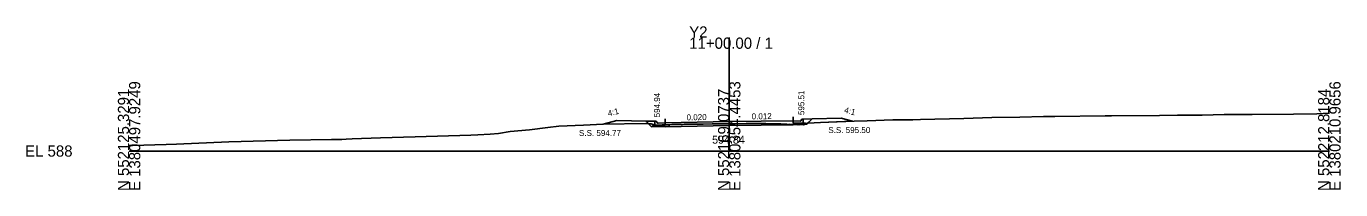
# Model space of a CAD drawing. Extents: x -26 to 303, y -10 to 2047.
# Drawn here: x -25.7 to 302.8, y 490.3 to 531.2 of the extents above; entities that cross this region are included whole.
import ezdxf

# ---------------------------------------------------------------- set-up
doc = ezdxf.new("R2010")
doc.units = 0
for name, color, linetype in [('Exist Cross Section Cell', 7, 'Continuous'), ('Exist XS Center Line Elevation Label', 7, 'Continuous'), ('Exist XS Ground Line', 7, 'Continuous'), ('Prop XS Dump Level', 7, 'Continuous'), ('Prop XS Earthwork Shape', 7, 'Continuous'), ('Prop XS EOT Tick Mark', 7, 'Continuous'), ('Prop XS Finish Grade', 7, 'Continuous'), ('Prop XS Finish Grade CurbGutter', 7, 'Continuous'), ('Prop XS Finish Grade Earthwork', 7, 'Continuous'), ('Prop XS Finish Grade Pavement', 7, 'Continuous'), ('Prop XS Hydro Elevations', 7, 'Continuous'), ('Prop XS Pvmt Edge Slope', 7, 'Continuous'), ('Prop XS SE Text', 7, 'Continuous'), ('Prop XS Side Slope Text', 7, 'Continuous'), ('Prop XS SS Elevation Text', 7, 'Continuous'), ('Prop XS Subgrade CurbGutter', 7, 'Continuous'), ('Prop XS Subgrade Earthwork', 7, 'Continuous')]:
    doc.layers.add(name, color=color, linetype=linetype)

msp = doc.modelspace()

# ---------------------------------------------------------------- linework, layer by layer
at = {"layer": 'Exist Cross Section Cell'}
for p, q in [((150, 500), (150, 528.41)), ((0, 500), (150, 500)), ((150, 500), (300, 500))]:
    msp.add_line(p, q, dxfattribs=at)
at = {"layer": 'Exist XS Ground Line'}
for p, q in [((280.7, 509.18), (291.03, 509.27)), ((291.03, 509.27), (296.84, 509.35)), ((296.84, 509.35), (300, 509.47)), ((104.7, 505.92), (107.39, 506.22)), ((107.39, 506.22), (113.6, 506.51)), ((113.6, 506.51), (118.53, 506.77)), ((118.53, 506.77), (129.05, 506.86)), ((129.05, 506.86), (130.51, 506.84)), ((130.51, 506.84), (131.6, 506.44)), ((131.6, 506.44), (133.25, 506.53)), ((133.25, 506.53), (135.12, 506.6)), ((135.12, 506.6), (135.66, 506.62)), ((135.66, 506.62), (136.01, 506.63)), ((136.01, 506.63), (137.19, 506.66)), ((137.19, 506.66), (138.29, 506.68)), ((138.29, 506.68), (138.77, 506.69)), ((138.77, 506.69), (140.9, 506.73)), ((140.9, 506.73), (142.03, 506.74)), ((142.03, 506.74), (143.51, 506.76)), ((143.51, 506.76), (145.74, 506.78)), ((145.74, 506.78), (146.31, 506.79)), ((146.31, 506.79), (148.73, 506.83)), ((148.73, 506.83), (150.04, 506.84)), ((150.04, 506.84), (151.33, 506.85)), ((151.33, 506.85), (154.27, 506.86)), ((154.27, 506.86), (156.55, 506.88)), ((156.55, 506.88), (157.55, 506.88)), ((157.55, 506.88), (159.17, 506.87)), ((159.17, 506.87), (160.03, 506.85)), ((160.03, 506.85), (161.77, 506.82)), ((161.77, 506.82), (162.89, 506.79)), ((162.89, 506.79), (164.05, 506.75)), ((164.05, 506.75), (164.41, 506.74)), ((164.41, 506.74), (166.2, 506.68)), ((166.2, 506.68), (166.81, 506.66)), ((166.81, 506.66), (168.52, 506.57)), ((168.52, 506.57), (169.6, 506.97)), ((169.6, 506.97), (172.79, 507.14)), ((172.79, 507.14), (181.26, 507.52)), ((181.26, 507.52), (184.44, 507.59)), ((184.44, 507.59), (190.9, 507.78)), ((190.9, 507.78), (194.87, 507.83)), ((194.87, 507.83), (195.92, 507.84)), ((195.92, 507.84), (197.84, 507.87)), ((197.84, 507.87), (208.6, 508.11)), ((208.6, 508.11), (215.65, 508.37)), ((215.65, 508.37), (222.67, 508.45)), ((222.67, 508.45), (228.56, 508.64)), ((228.56, 508.64), (231.39, 508.69)), ((231.39, 508.69), (243.98, 508.79)), ((243.98, 508.79), (245.55, 508.81)), ((245.55, 508.81), (257.55, 508.92)), ((257.55, 508.92), (262.08, 509.01)), ((262.08, 509.01), (268.22, 509.02)), ((268.22, 509.02), (273.71, 509.13)), ((273.71, 509.13), (279.21, 509.19)), ((279.21, 509.19), (280.7, 509.18)), ((24.93, 502.27), (40.2, 502.72)), ((40.2, 502.72), (50.57, 502.93)), ((50.57, 502.93), (53.21, 502.93)), ((53.21, 502.93), (54.3, 502.96)), ((54.3, 502.96), (55.8, 503.04)), ((55.8, 503.04), (62.82, 503.27)), ((62.82, 503.27), (71.48, 503.57)), ((71.48, 503.57), (85.38, 503.97)), ((85.38, 503.97), (87.17, 504.02)), ((87.17, 504.02), (90.21, 504.26)), ((90.21, 504.26), (92.35, 504.42)), ((92.35, 504.42), (95.26, 504.87)), ((95.26, 504.87), (100.11, 505.35)), ((100.11, 505.35), (104.7, 505.92)), ((0, 501.35), (0.85, 501.38)), ((0.85, 501.38), (9.3, 501.65)), ((9.3, 501.65), (11.83, 501.72)), ((11.83, 501.72), (24.93, 502.27))]:
    msp.add_line(p, q, dxfattribs=at)
at = {"layer": 'Prop XS Dump Level'}
for p, q in [((133.95, 507.06), (150, 507.38)), ((133.95, 506.06), (150, 506.38)), ((150, 507.38), (166.01, 507.57)), ((150, 506.38), (166.01, 506.57))]:
    msp.add_line(p, q, dxfattribs=at)
at = {"layer": 'Prop XS Earthwork Shape'}
for points in [[(121.95, 507.64), (118.46, 506.77), (118.53, 506.77), (129.05, 506.86), (129.84, 506.85), (129.21, 507.48)], [(134.95, 506.16), (130.61, 506.08), (129.84, 506.85), (130.51, 506.84), (131.6, 506.44), (133.25, 506.53), (134.95, 506.59)], [(165.01, 506.64), (165.01, 506.72), (166.2, 506.68), (166.81, 506.66), (166.84, 506.66)], [(168.52, 506.57), (168.84, 506.68), (166.84, 506.66)], [(169.6, 506.97), (169.62, 506.97), (169.34, 506.69), (168.84, 506.68)], [(170.71, 508.05), (178.01, 508.21), (180.83, 507.5), (172.79, 507.14), (169.62, 506.97)]]:
    msp.add_lwpolyline(points, close=True, dxfattribs=at)
at = {"layer": 'Prop XS EOT Tick Mark'}
for p, q in [((133.95, 507.06), (133.95, 508.06)), ((166.01, 507.57), (166.01, 508.57))]:
    msp.add_line(p, q, dxfattribs=at)
at = {"layer": 'Prop XS Finish Grade'}
for p, q in [((131.45, 507.44), (129.21, 507.48)), ((168.51, 508.01), (170.71, 508.05))]:
    msp.add_line(p, q, dxfattribs=at)
at = {"layer": 'Prop XS Finish Grade CurbGutter'}
for p, q in [((131.45, 507.44), (131.7, 507.44)), ((131.7, 507.44), (131.82, 507.41)), ((131.91, 507.32), (131.82, 507.41)), ((131.98, 507.07), (131.91, 507.32)), ((132.07, 506.98), (131.98, 507.07)), ((132.2, 506.95), (132.07, 506.98)), ((133.95, 507.06), (132.2, 506.95)), ((166.01, 507.57), (167.76, 507.52)), ((167.76, 507.52), (167.88, 507.54)), ((167.88, 507.54), (167.97, 507.63)), ((167.97, 507.63), (168.04, 507.88)), ((168.04, 507.88), (168.13, 507.97)), ((168.26, 508.01), (168.13, 507.97)), ((168.51, 508.01), (168.26, 508.01))]:
    msp.add_line(p, q, dxfattribs=at)
at = {"layer": 'Prop XS Finish Grade Earthwork'}
for p, q in [((121.95, 507.64), (118.46, 506.77)), ((129.21, 507.48), (121.95, 507.64)), ((170.71, 508.05), (178.01, 508.21)), ((178.01, 508.21), (180.83, 507.5))]:
    msp.add_line(p, q, dxfattribs=at)
at = {"layer": 'Prop XS Finish Grade Pavement'}
for p, q in [((133.95, 507.06), (150, 507.38)), ((150, 507.38), (166.01, 507.57))]:
    msp.add_line(p, q, dxfattribs=at)
at = {"layer": 'Prop XS Pvmt Edge Slope'}
for p, q in [((130.95, 506.42), (130.61, 506.08)), ((131.45, 506.43), (130.95, 506.42)), ((168.51, 507.01), (169.01, 507.02)), ((169.01, 507.02), (169.34, 506.69))]:
    msp.add_line(p, q, dxfattribs=at)
at = {"layer": 'Prop XS Subgrade CurbGutter'}
for p, q in [((131.45, 506.43), (131.45, 507.44)), ((133.95, 506.48), (131.45, 506.43)), ((133.95, 507.06), (133.95, 506.48)), ((166.01, 507.57), (166.01, 506.99)), ((166.01, 506.99), (168.51, 507.01)), ((168.51, 507.01), (168.51, 508.01))]:
    msp.add_line(p, q, dxfattribs=at)
at = {"layer": 'Prop XS Subgrade Earthwork'}
for p, q in [((130.61, 506.08), (129.21, 507.48)), ((134.95, 506.16), (130.61, 506.08)), ((133.95, 506.14), (133.95, 506.14)), ((134.95, 506.16), (134.95, 506.59)), ((165.01, 506.64), (165.01, 506.72)), ((165.01, 506.64), (169.34, 506.69)), ((166.01, 506.65), (166.01, 506.65)), ((169.34, 506.69), (170.71, 508.05))]:
    msp.add_line(p, q, dxfattribs=at)

# ---------------------------------------------------------------- texts
at = {"layer": 'Exist Cross Section Cell'}
for s, p in [('Y2', (140, 528.41)), ('11+00.00 / 1', (140, 525.61)), ('EL 588', (-26, 498.6))]:
    msp.add_text(s, height=2.8, dxfattribs=at).set_placement(p)
for s, p in [('E 1380497.9249', (2.8, 490)), ('E 1380354.4453', (152.8, 490)), ('E 1380210.9656', (302.8, 490)), ('N 552125.3291', (0, 490)), ('N 552169.0737', (150, 490)), ('N 552212.8184', (300, 490))]:
    msp.add_text(s, height=2.8, rotation=90, dxfattribs=at).set_placement(p)
at = {"layer": 'Exist XS Center Line Elevation Label'}
msp.add_text('594.84', height=2, dxfattribs=at).set_placement((145.72, 501.84))
at = {"layer": 'Prop XS Dump Level'}
for p in [(133.25, 506.23), (166.81, 506.36)]:
    msp.add_text('Eop', height=0.3, dxfattribs=at).set_placement(p)
at = {"layer": 'Prop XS Hydro Elevations'}
for s, p in [('594.94', (132.7, 508.44)), ('595.51', (168.76, 509.01))]:
    msp.add_text(s, height=1.5, rotation=90, dxfattribs=at).set_placement(p)
at = {"layer": 'Prop XS SE Text'}
for s, rotation, p in [('0.020', 1.1458, (139.35, 507.67)), ('0.012', 0.6684, (155.62, 507.94))]:
    msp.add_text(s, height=1.5, rotation=rotation, dxfattribs=at).set_placement(p)
at = {"layer": 'Prop XS Side Slope Text'}
for rotation, p in [(14.0362, (119.84, 508.66)), (345.9638, (178.63, 509.6))]:
    msp.add_text('4:1', height=1.5, rotation=rotation, dxfattribs=at).set_placement(p)
at = {"layer": 'Prop XS SS Elevation Text'}
for s, p in [('S.S. 595.50', (174.77, 504.5)), ('S.S. 594.77', (112.46, 503.77))]:
    msp.add_text(s, height=1.5, dxfattribs=at).set_placement(p)

doc.saveas('drawing.dxf')
